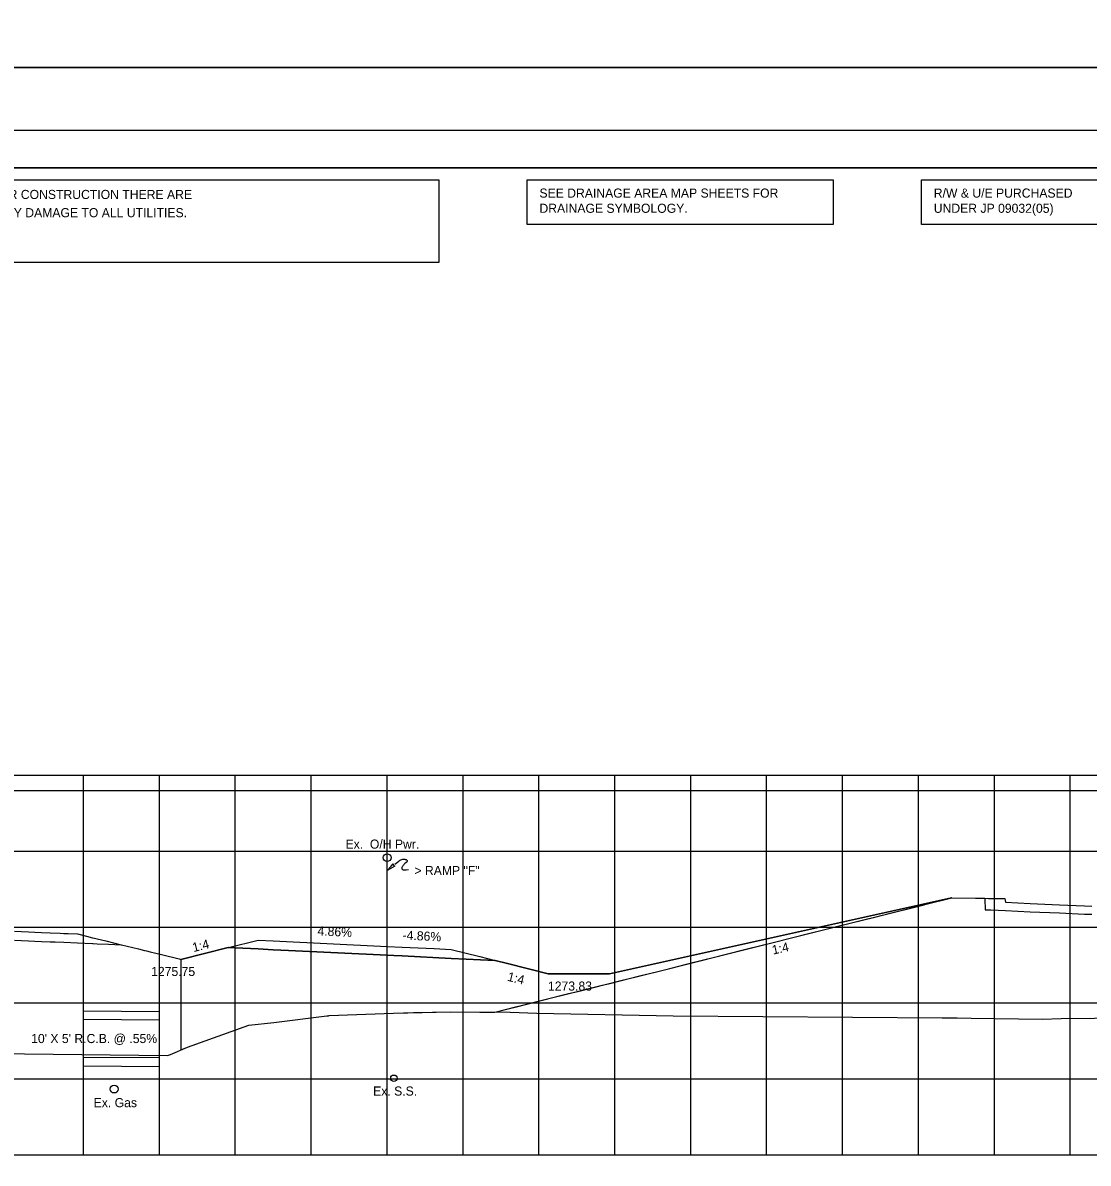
# Model space of a CAD drawing. Extents: x 2148105 to 2149976, y 144169 to 149705.
# Drawn here: x 2148365.3 to 2148505.7, y 148120.8 to 148271 of the extents above; entities that cross this region are included whole.
import ezdxf

# ---------------------------------------------------------------- set-up
doc = ezdxf.new("R2010")
doc.units = 0
for name, color, linetype in [('Bridge M-Header', 7, 'Continuous'), ('Default', 7, 'Continuous'), ('INR_Tracking', 7, 'Continuous'), ('Ph1-PR-Ramp SF3 Rev-Curb', 7, 'Continuous'), ('PH1a-2-RampC', 7, 'Continuous'), ('PH1a-PR-DividingStrip', 7, 'Continuous'), ('PH1a-PR-ServRd', 7, 'Continuous'), ('PH2-PR-Barrier', 7, 'Continuous'), ('PR-ApproachSlab', 7, 'Continuous'), ('PR-SHLDR-RMP-H', 7, 'Continuous'), ('PR_Align_Ramp_E', 7, 'Continuous'), ('PR_Align_Ramp_J', 7, 'Continuous'), ('PR_Storm_Channel', 7, 'Continuous'), ('PR_Storm_Conc_Box_PH1B', 7, 'Continuous'), ('PR_Storm_Conc_Pipe', 7, 'Continuous'), ('PR_Storm_Conc_Pipe_PH1B', 7, 'Continuous'), ('PR_Storm_Inlet_CICI_PH1B', 7, 'Continuous'), ('PR_Storm_Junction_Box_PH1A', 7, 'Continuous'), ('PR_Storm_MH', 7, 'Continuous'), ('PR_Storm_Standard_Median_Drain_PH1B', 7, 'Continuous'), ('PR_Storm_Txt_PH1B', 7, 'Continuous'), ('TopCut', 7, 'Continuous'), ('TOPO_Asphalt', 7, 'Continuous'), ('TOPO_DRAIN_Structure', 7, 'Continuous')]:
    doc.layers.add(name, color=color, linetype=linetype)

# ---------------------------------------------------------------- blocks, each defined once
blk = doc.blocks.new('POINT_DISPLAY')
at = {"layer": 'Default'}
blk.add_line((0, 0), (0, 0), dxfattribs=at)

msp = doc.modelspace()

# ---------------------------------------------------------------- linework, layer by layer
at = {"layer": 'INR_Tracking'}
msp.add_lwpolyline([(2148386.16, 148147.66), (2148392.4, 148149.22), (2148392.41, 148149.22), (2148394.33, 148149.13), (2148394.33, 148149.13), (2148396.32, 148149.03), (2148398.32, 148148.93), (2148398.32, 148148.93), (2148400.33, 148148.83), (2148413.32, 148148.2), (2148413.34, 148148.2), (2148414.19, 148148.16), (2148415.31, 148148.11), (2148415.32, 148148.11), (2148421.74, 148147.79), (2148421.74, 148147.79), (2148423.72, 148147.7), (2148423.73, 148147.7), (2148427.53, 148147.51), (2148427.54, 148147.51), (2148429.17, 148147.1), (2148434.53, 148145.76), (2148434.64, 148145.74), (2148442.07, 148145.74), (2148442.64, 148145.74), (2148487.68, 148155.77), (2148487.73, 148155.78)], dxfattribs=at)
at = {"layer": 'Ph1-PR-Ramp SF3 Rev-Curb'}
for points in [[(2148373.32, 148140.86), (2148383.32, 148140.8)], [(2148373.32, 148139.78), (2148383.32, 148139.71)], [(2148373.32, 148134.78), (2148383.32, 148134.71)], [(2148373.32, 148133.61), (2148383.32, 148133.55)]]:
    msp.add_lwpolyline(points, dxfattribs=at)
at = {"layer": 'PH1a-PR-ServRd'}
msp.add_lwpolyline([(2148570.82, 148041.91), (2148255.82, 148041.91), (2148255.82, 148251.91), (2148570.82, 148251.91)], close=True, dxfattribs=at)
at = {"layer": 'PH2-PR-Barrier'}
msp.add_line((2148413.32, 148149.37), (2148413.32, 148159.37), dxfattribs=at)
for points in [[(2148414.33, 148160.18), (2148414.69, 148160.47), (2148414.85, 148160.6), (2148414.94, 148160.68), (2148415.04, 148160.73), (2148415.14, 148160.78), (2148415.26, 148160.82), (2148415.39, 148160.85), (2148415.49, 148160.85), (2148415.57, 148160.85), (2148415.65, 148160.85), (2148415.72, 148160.83), (2148415.78, 148160.82), (2148415.83, 148160.8), (2148415.87, 148160.77), (2148415.91, 148160.74), (2148415.95, 148160.7), (2148415.98, 148160.64), (2148415.97, 148160.58), (2148415.96, 148160.54), (2148415.91, 148160.47), (2148415.72, 148160.31), (2148415.53, 148160.15), (2148415.46, 148160.07), (2148415.39, 148160), (2148415.33, 148159.9), (2148415.29, 148159.84), (2148415.25, 148159.75), (2148415.25, 148159.68), (2148415.27, 148159.59), (2148415.31, 148159.52), (2148415.36, 148159.49), (2148415.42, 148159.47), (2148415.53, 148159.45), (2148415.66, 148159.46), (2148415.82, 148159.47), (2148416.15, 148159.51)], [(2148413.32, 148159.37), (2148413.84, 148159.92), (2148414.1, 148160.23), (2148414.18, 148160.06), (2148414.32, 148159.94), (2148413.32, 148159.37)]]:
    msp.add_lwpolyline(points, dxfattribs=at)
at = {"layer": 'PR-ApproachSlab'}
msp.add_lwpolyline([(2148427.53, 148140.71), (2148429.79, 148141.27), (2148430.01, 148141.33), (2148435.49, 148142.7), (2148436.27, 148142.9), (2148441.14, 148144.12), (2148441.65, 148144.24), (2148442.48, 148144.45), (2148446.74, 148145.52), (2148448.63, 148145.99), (2148452.3, 148146.91), (2148454.72, 148147.51), (2148457.82, 148148.29), (2148460.77, 148149.03), (2148464.36, 148149.93), (2148466.76, 148150.53), (2148470.99, 148151.59), (2148472.72, 148152.02), (2148477.57, 148153.23), (2148478.59, 148153.49), (2148484.06, 148154.86), (2148484.16, 148154.88), (2148484.52, 148154.97), (2148487.73, 148155.78), (2148490.86, 148155.72), (2148492.06, 148155.7), (2148492.54, 148155.69), (2148494.12, 148155.67), (2148494.12, 148155.67), (2148494.13, 148155.67), (2148494.43, 148155.67), (2148494.72, 148155.67), (2148494.76, 148155.4), (2148494.8, 148155.17), (2148494.8, 148155.17), (2148494.8, 148155.17), (2148498.06, 148155.03), (2148501.9, 148154.86), (2148505.18, 148154.71), (2148506.15, 148154.67)], dxfattribs=at)
at = {"layer": 'PR-SHLDR-RMP-H'}
msp.add_lwpolyline([(2148427.53, 148140.71), (2148430.42, 148141.43), (2148430.63, 148141.48), (2148437.23, 148143.14), (2148438.43, 148143.44), (2148444.11, 148144.86), (2148446.15, 148145.37), (2148450.92, 148146.56), (2148453.79, 148147.28), (2148457.67, 148148.25), (2148461.35, 148149.17), (2148464.36, 148149.93), (2148468.84, 148151.05), (2148470.99, 148151.59), (2148476.25, 148152.9), (2148477.55, 148153.23), (2148483.6, 148154.74), (2148483.6, 148154.74), (2148483.71, 148154.77), (2148484.16, 148154.88), (2148487.73, 148155.78), (2148490.86, 148155.72), (2148492.06, 148155.7), (2148492.07, 148155.42), (2148492.07, 148155.37), (2148492.08, 148155.37), (2148492.08, 148155.37), (2148492.08, 148155.23), (2148492.11, 148154.54), (2148492.11, 148154.26), (2148492.12, 148154.2), (2148492.86, 148154.17), (2148494.8, 148154.09), (2148494.8, 148154.09), (2148494.8, 148154.09), (2148498.06, 148153.94), (2148501.9, 148153.77), (2148505.18, 148153.63), (2148506.15, 148153.59)], dxfattribs=at)
at = {"layer": 'PR_Align_Ramp_E'}
for points in [[(2148219.95, 148505.16), (2148579.95, 148505.16), (2148579.95, 148265.16), (2148219.95, 148265.16)], [(2148219.95, 148265.16), (2148579.95, 148265.16), (2148579.95, 148025.16), (2148219.95, 148025.16)]]:
    msp.add_lwpolyline(points, close=True, dxfattribs=at)
at = {"layer": 'PR_Align_Ramp_J'}
msp.add_lwpolyline([(2148236.32, 148256.91), (2148576.32, 148256.91), (2148576.32, 148036.91), (2148236.32, 148036.91)], close=True, dxfattribs=at)
at = {"layer": 'PR_Storm_Channel'}
msp.add_lwpolyline([(2148392.41, 148149.22), (2148396.32, 148150.2), (2148398.32, 148150.1), (2148413.32, 148149.37), (2148415.32, 148149.27), (2148419.5, 148149.07), (2148421.74, 148148.96), (2148425.52, 148148.02), (2148427.54, 148147.51)], dxfattribs=at)
at = {"layer": 'PR_Storm_Conc_Box_PH1B'}
for p, q in [((2148263.32, 148171.91), (2148563.32, 148171.91)), ((2148373.32, 148121.91), (2148373.32, 148171.91)), ((2148383.32, 148121.91), (2148383.32, 148171.91)), ((2148393.32, 148121.91), (2148393.32, 148171.91)), ((2148403.32, 148121.91), (2148403.32, 148171.91)), ((2148413.32, 148121.91), (2148413.32, 148171.91)), ((2148423.32, 148121.91), (2148423.32, 148171.91)), ((2148433.32, 148121.91), (2148433.32, 148171.91)), ((2148443.32, 148121.91), (2148443.32, 148171.91)), ((2148453.32, 148121.91), (2148453.32, 148171.91)), ((2148463.32, 148121.91), (2148463.32, 148171.91)), ((2148473.32, 148121.91), (2148473.32, 148171.91)), ((2148483.32, 148121.91), (2148483.32, 148171.91)), ((2148493.32, 148121.91), (2148493.32, 148171.91)), ((2148503.32, 148121.91), (2148503.32, 148171.91)), ((2148263.32, 148161.91), (2148563.32, 148161.91)), ((2148263.32, 148151.91), (2148563.32, 148151.91)), ((2148263.32, 148141.91), (2148563.32, 148141.91)), ((2148263.32, 148131.91), (2148563.32, 148131.91)), ((2148263.32, 148121.91), (2148563.32, 148121.91))]:
    msp.add_line(p, q, dxfattribs=at)
at = {"layer": 'PR_Storm_Conc_Pipe'}
msp.add_lwpolyline([(2148364.24, 148150.19), (2148366.08, 148150.11), (2148366.92, 148150.07), (2148367.78, 148150.03), (2148368.94, 148149.98), (2148369.58, 148149.96), (2148370.72, 148149.91), (2148372.53, 148149.83), (2148374.52, 148149.75), (2148374.6, 148149.74), (2148375.14, 148149.72), (2148376.6, 148149.66), (2148378.3, 148149.58), (2148378.32, 148149.58), (2148378.32, 148149.58), (2148380.56, 148149.03), (2148381.34, 148148.84), (2148381.64, 148148.76), (2148382.12, 148148.64), (2148383.61, 148148.28), (2148385.93, 148147.71), (2148386.16, 148147.65)], dxfattribs=at)
at = {"layer": 'PR_Storm_Conc_Pipe_PH1B'}
msp.add_lwpolyline([(2148255.82, 148041.91), (2148570.82, 148041.91), (2148570.82, 148251.91), (2148255.82, 148251.91)], close=True, dxfattribs=at)
msp.add_lwpolyline([(2148255.82, 148041.91), (2148570.82, 148041.91), (2148570.82, 148251.91), (2148255.82, 148251.91)], close=True, dxfattribs=at)
at = {"layer": 'PR_Storm_Inlet_CICI_PH1B'}
msp.add_lwpolyline([(2148358.03, 148135.3), (2148365.56, 148135.2), (2148384.37, 148135.01), (2148384.78, 148135.13), (2148387.01, 148136.11), (2148395.11, 148138.97), (2148398.38, 148139.35), (2148405.39, 148140.22), (2148405.6, 148140.24), (2148405.68, 148140.26), (2148414.15, 148140.58), (2148421.65, 148140.76), (2148429.54, 148140.69), (2148433.05, 148140.57), (2148451, 148140.22), (2148486.43, 148139.96), (2148487.77, 148139.95), (2148488.42, 148139.96), (2148490.25, 148139.92), (2148499.64, 148139.8), (2148502.12, 148139.85), (2148519.75, 148140.06)], dxfattribs=at)
at = {"layer": 'PR_Storm_Junction_Box_PH1A'}
for centre in [(2148413.32, 148161.06), (2148377.36, 148130.57)]:
    msp.add_circle(centre, 0.516, dxfattribs=at)
at = {"layer": 'PR_Storm_MH'}
for points in [[(2148257.69, 148250.34), (2148420.12, 148250.34), (2148420.12, 148239.47), (2148257.69, 148239.47)], [(2148431.78, 148250.34), (2148472.07, 148250.34), (2148472.07, 148244.47), (2148431.78, 148244.47)], [(2148483.72, 148250.34), (2148509.15, 148250.34), (2148509.15, 148244.47), (2148483.72, 148244.47)]]:
    msp.add_lwpolyline(points, close=True, dxfattribs=at)
at = {"layer": 'PR_Storm_Standard_Median_Drain_PH1B'}
msp.add_line((2148263.32, 148121.91), (2148563.32, 148121.91), dxfattribs=at)
at = {"layer": 'PR_Storm_Txt_PH1B'}
msp.add_lwpolyline([(2148364.24, 148151.35), (2148366.08, 148151.27), (2148366.92, 148151.24), (2148367.78, 148151.2), (2148368.94, 148151.15), (2148370.23, 148151.1), (2148370.72, 148151.08), (2148371.29, 148151.05), (2148372.53, 148151), (2148373.73, 148150.7), (2148374.52, 148150.51), (2148374.76, 148150.45), (2148375.14, 148150.36), (2148376.26, 148150.08), (2148378.3, 148149.58)], dxfattribs=at)
at = {"layer": 'TopCut'}
msp.add_lwpolyline([(2148386.16, 148147.66), (2148386.16, 148135.73), (2148387.01, 148136.11), (2148395.11, 148138.97), (2148398.38, 148139.35), (2148405.39, 148140.22), (2148405.6, 148140.24), (2148405.68, 148140.26), (2148414.15, 148140.58), (2148416.8, 148140.64), (2148417.92, 148140.67), (2148419.28, 148140.7), (2148421.65, 148140.76), (2148425.53, 148140.72), (2148426.81, 148140.71), (2148427.53, 148140.71), (2148430.42, 148141.43), (2148430.63, 148141.48), (2148437.23, 148143.14), (2148438.43, 148143.44), (2148444.11, 148144.86), (2148446.15, 148145.37), (2148450.92, 148146.56), (2148453.79, 148147.28), (2148457.67, 148148.25), (2148461.35, 148149.17), (2148464.36, 148149.93), (2148468.84, 148151.05), (2148470.99, 148151.59), (2148476.25, 148152.9), (2148477.55, 148153.23), (2148483.6, 148154.74), (2148483.6, 148154.74), (2148483.71, 148154.77), (2148484.16, 148154.88), (2148487.73, 148155.78), (2148487.68, 148155.77), (2148442.64, 148145.74), (2148442.07, 148145.74), (2148434.64, 148145.74), (2148434.53, 148145.76), (2148429.17, 148147.1), (2148427.54, 148147.51), (2148427.53, 148147.51), (2148423.73, 148147.7), (2148423.72, 148147.7), (2148421.74, 148147.79), (2148421.74, 148147.79), (2148415.32, 148148.11), (2148415.31, 148148.11), (2148414.19, 148148.16), (2148413.34, 148148.2), (2148413.32, 148148.2), (2148400.33, 148148.83), (2148398.32, 148148.93), (2148398.32, 148148.93), (2148396.32, 148149.03), (2148394.33, 148149.13), (2148394.33, 148149.13), (2148392.41, 148149.22), (2148392.4, 148149.22)], close=True, dxfattribs=at)
at = {"layer": 'TOPO_Asphalt'}
msp.add_line((2148263.32, 148169.91), (2148563.32, 148169.91), dxfattribs=at)
at = {"layer": 'TOPO_DRAIN_Structure'}
msp.add_circle((2148414.21, 148132), 0.417, dxfattribs=at)

# ---------------------------------------------------------------- block references
at = {"layer": 'PR_Storm_Conc_Pipe_PH1B', "xscale": 10, "yscale": 10}
for p in [(2148398.32, 148150.1), (2148398.32, 148150.1), (2148415.32, 148149.27), (2148415.32, 148149.27), (2148421.74, 148148.96), (2148421.74, 148148.96)]:
    msp.add_blockref('POINT_DISPLAY', p, dxfattribs=at)

# ---------------------------------------------------------------- texts
at = {"layer": 'Bridge M-Header'}
for s, p in [('4.86%', (2148404.12, 148150.82)), ('-4.86%', (2148415.34, 148150.27))]:
    msp.add_text(s, height=1.2, rotation=357.2184, dxfattribs=at).set_placement(p)
at = {"layer": 'PH1a-2-RampC'}
for s, p in [('1275.75', (2148382.23, 148145.46)), ('1273.83', (2148434.51, 148143.54)), ("10' X 5' R.C.B. @ .55%", (2148366.42, 148136.63))]:
    msp.add_text(s, height=1.2, dxfattribs=at).set_placement(p)
at = {"layer": 'PH1a-PR-DividingStrip'}
for rotation, p in [(14.0351, (2148387.82, 148148.61)), (12.556, (2148464.17, 148148.28)), (345.9613, (2148429.08, 148144.86))]:
    msp.add_text('1:4', height=1.2, rotation=rotation, dxfattribs=at).set_placement(p)
at = {"layer": 'PH2-PR-Barrier'}
msp.add_text('> RAMP "F"', height=1.2, rotation=360, dxfattribs=at).set_placement((2148416.92, 148158.76))
at = {"layer": 'PR_Storm_Junction_Box_PH1A'}
for s, p in [('Ex.  O/H Pwr.', (2148407.84, 148162.24)), ('Ex. S.S.', (2148411.48, 148129.71)), ('Ex. Gas', (2148374.66, 148128.18))]:
    msp.add_text(s, height=1.2, rotation=360, dxfattribs=at).set_placement(p)
at = {"layer": 'PR_Storm_MH'}
for s, p in [('SEE DRAINAGE AREA MAP SHEETS FOR', (2148433.39, 148248)), ('R/W & U/E PURCHASED', (2148485.34, 148248)), ("(CAUTION) THE LOCATION OF ALL UTILITIES AS SHOWN ARE APPROXIMATE. DUE TO RELOCATION'S PLANNED OR PRESENTLY UNDER CONSTRUCTION THERE ARE ", (2148258.92, 148247.82)), ('SOME UTILITIES THAT WILL BE RELOCATED AND NOT SHOWN ON THESE PLANS. THE CONTRACTOR SHALL BE RESPONSIBLE FOR ANY DAMAGE TO ALL UTILITIES.', (2148258.92, 148245.42)), ('DRAINAGE SYMBOLOGY.', (2148433.39, 148246)), ('UNDER JP 09032(05)', (2148485.34, 148246))]:
    msp.add_text(s, height=1.2, dxfattribs=at).set_placement(p)

doc.saveas('drawing.dxf')
